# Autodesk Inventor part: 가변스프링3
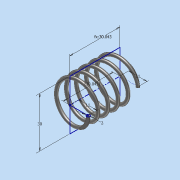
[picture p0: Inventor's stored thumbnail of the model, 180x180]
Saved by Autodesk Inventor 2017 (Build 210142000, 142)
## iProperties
Part Number: 가변스프링3
Material: 강철, 연강
Document SubType Name: Modeling
Designer: MRC
Density: 7.85 g/cm^3
Appearance: 반연마
Mass: 8.40322 g
Surface Area: 21.6867 cm^2
Volume: 1.07047 cm^3
Author: MRC
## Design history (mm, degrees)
sketch "스케치1"
  geometry: L1 (0, 0)-(0, 30.043); L2 (0, 0)-(11, 0); L3 (0, 30.043)-(11, 30.043); C1 r 1 at (11, 0)
  constraints: 6 end point, 1 centre point, 1 coincident, 1 horizontal, 1 parallel, 1 vertical
  dimensions: "d1" = 11 distance of L1.start L2.end; "d2" = 11 distance of L1.end L3.end; "d3" = 2 diameter of C1; "d4" = 30.04259 distance of L1.start L1.end (derived)
feature "코일1" sketch "스케치1" pitch "d5" = 10; turns "d7" = 5; dims "d6" = 30.04259 (= d4), "d8" = 0, angle "d9" = 90 deg, angle "d10" = 90 deg, "d11" = 0, "d12" = 0
sketch "스케치2"
  geometry: L1 (30.043, -15)-(0, -15); L2 (0, -15)-(0, 15); L3 (0, 15)-(30.043, 15); L4 (30.043, 15)-(30.043, -15); 2 further points
  constraints: 8 end point, 2 parallel, 1 coincident, 1 horizontal, 1 midpoint, 1 perpendicular
  dimensions: "d13" = 30.04259 distance of L2.end L3.end (= d4); "d14" = 30 distance of L1.end L2.end
extrude "돌출1" sketch "스케치2" stored distance "d15" = 0; taper "d16" = 0 deg
node "솔리드1"
